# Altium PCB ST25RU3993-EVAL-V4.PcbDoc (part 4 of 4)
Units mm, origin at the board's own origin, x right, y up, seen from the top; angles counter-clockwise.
Board outline 76.25 x 96.25 mm, 6 copper layers (Top Layer, RF GND, Power, GND, Routing, Bottom GND), stack 1.022 mm thick; 319 components, 214 nets, 994 pads, 1429 vias.
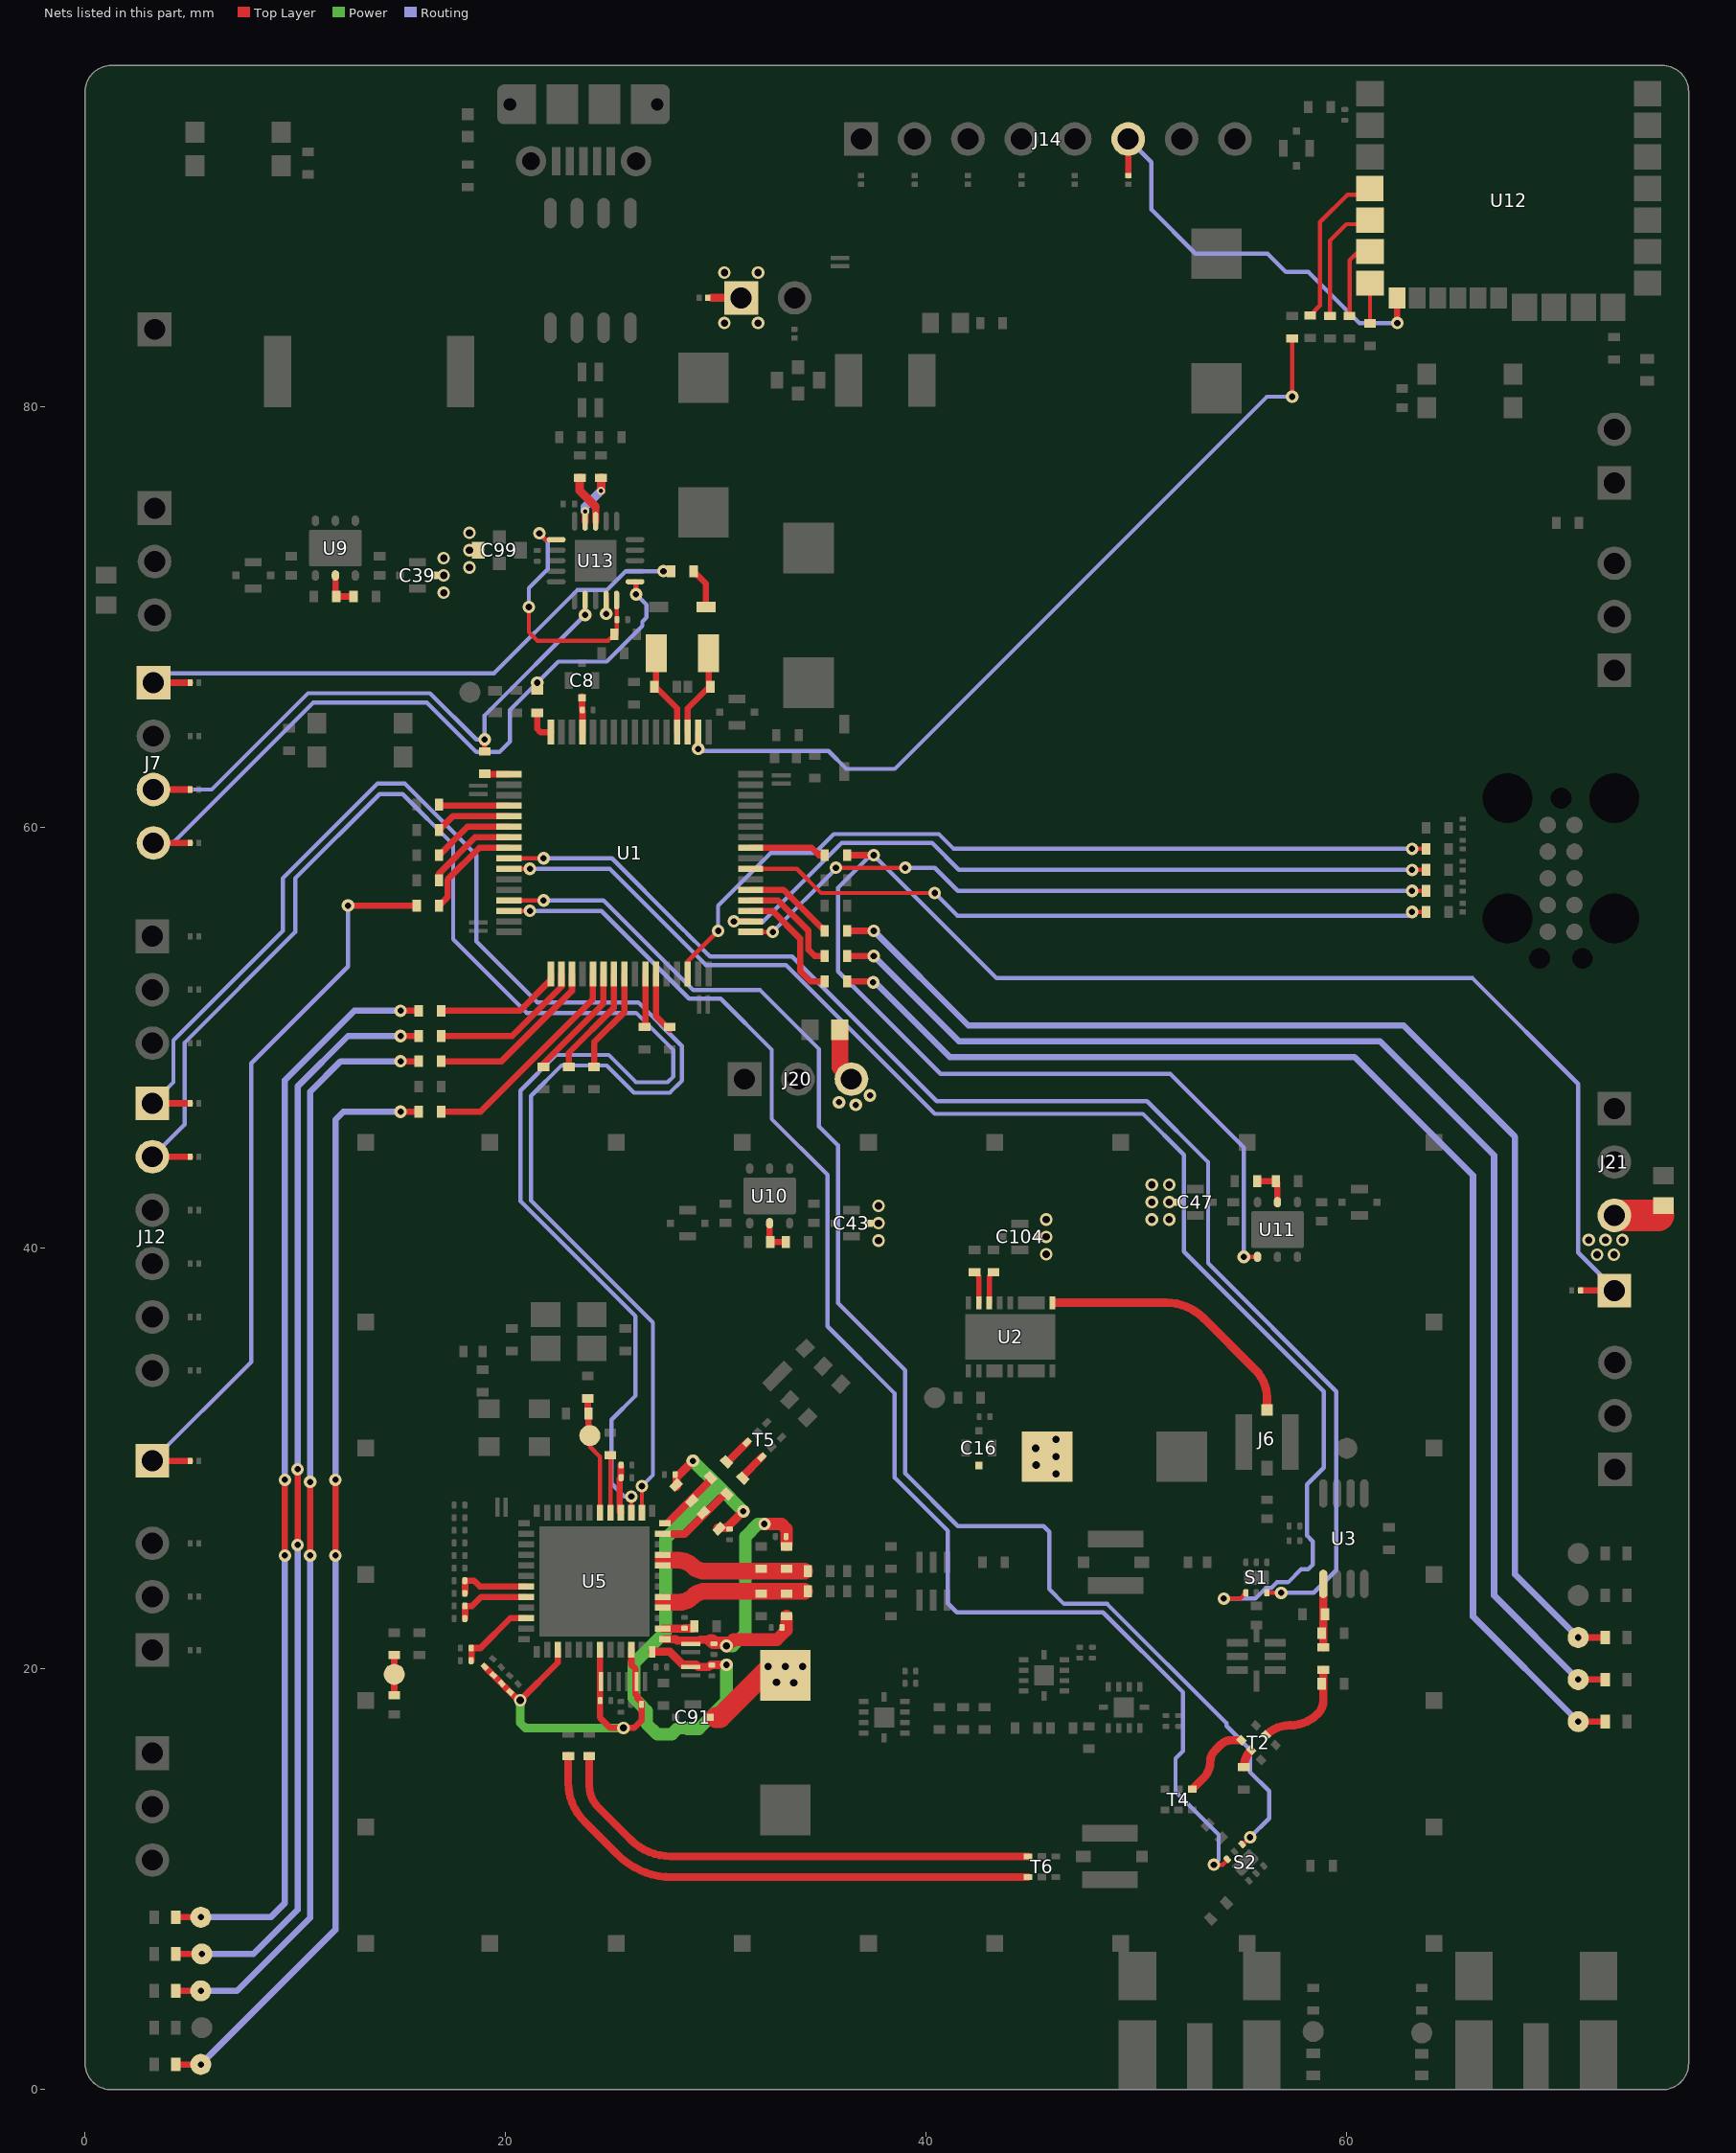
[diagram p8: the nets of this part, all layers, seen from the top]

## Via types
v1: diameter 0.6, hole 0.3, Top Layer to Bottom GND, tented both sides, 407 vias
v2: diameter 0.35, hole 0.35, Top Layer to Bottom GND, tented both sides, 245 vias
v3: diameter 0.61, hole 0.3, Top Layer to Bottom GND, tented both sides, 240 vias
v4: diameter 0.3, hole 0.3, Top Layer to Bottom GND, tented both sides, 105 vias
v5: diameter 0.4, hole 0.3, Top Layer to Bottom GND, tented both sides, 93 vias
v6: diameter 0.6/0.6/0.6/0.6/0.6/0.6 (per signal layer), hole 0.35, Top Layer to Bottom GND, tented both sides, 92 vias
v7: diameter 0.6, hole 0.35, Top Layer to Bottom GND, tented both sides, 71 vias
v8: diameter 0.2, hole 0.2, Top Layer to Bottom GND, tented both sides, 60 vias
v9: diameter 0.4, hole 0.2, Top Layer to Bottom GND, 45 vias
v10: diameter 0.6, hole 0.35, Top Layer to Bottom GND, 16 vias
v11: diameter 0.66, hole 0.33, Top Layer to Bottom GND, tented both sides, 16 vias
v12: diameter 0.35, hole 0.3, Top Layer to Bottom GND, tented both sides, 10 vias
v13: diameter 0.4, hole 0.4, Top Layer to Bottom GND, tented both sides, 6 vias
v14: diameter 1.8/2.51/2.51/2.51/2.51/2.51 (per signal layer), hole 1.71, Top Layer to Bottom GND, 6 vias
v15: diameter 0.5, hole 0.2, Top Layer to Bottom GND, 4 vias
v16: diameter 0.6, hole 0.3, Top Layer to Bottom GND, tented bottom, 4 vias
v17: diameter 0.5, hole 0.3, Top Layer to Bottom GND, tented both sides, 2 vias
v18: diameter 1.8/1.8/1.8/1.8/1.8/2.51 (per signal layer), hole 1.71, Top Layer to Bottom GND, 2 vias
v19: diameter 0.6, hole 0.2, Top Layer to Bottom GND, tented both sides, 2 vias
v20: diameter 0.4, hole 0.2, Top Layer to Bottom GND, tented both sides, 2 vias
v21: diameter 0.8, hole 0.4, Top Layer to Bottom GND, tented both sides, 1 vias

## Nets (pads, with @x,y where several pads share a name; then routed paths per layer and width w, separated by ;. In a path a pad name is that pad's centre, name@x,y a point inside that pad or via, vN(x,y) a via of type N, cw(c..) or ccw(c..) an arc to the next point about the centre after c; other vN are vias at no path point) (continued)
NetR4_2: R4.2 U1.50 | length 35.8
  Top Layer w0.2: v1(63.1,58) R4.2@63.767,58
  Top Layer w0.3: v1(30.85,55.55) U1.50@31.65,55.55
  Routing w0.2: v1(30.85,55.55) 32.25,55.55 35.975,59.275 40.275,59.275 41.55,58 v1(63.1,58)
NetR7_2: R7.2 U1.20 | length 3.3
  Top Layer w0.3: R7.2@16.833,61.1 16.883,61.05 U1.20@20.15,61.05
NetR8_2: R8.2 U1.21 | length 3.6
  Top Layer w0.3: R8.2@16.833,59.9 17.483,60.55 U1.21@20.15,60.55
NetR9_2: R9.2 U1.22 | length 3.9
  Top Layer w0.3: R9.2@16.833,58.7 18.183,60.05 U1.22@20.15,60.05
NetR10_1: R10.1 U2.11 | length 1.5
  Top Layer w0.25: U2.11@43,37.42 43,38.667 R10.1@43.2,38.867
NetR11_2: R11.2 U1.23 | length 4.4
  Top Layer w0.3: R11.2@16.833,57.5 16.833,57.833 18.55,59.55 U1.23@20.15,59.55
NetR12_2: R12.2 U1.42 | length 2.5
  Top Layer w0.3: R12.2@26.6,50.533 26.65,50.583 U1.42@26.65,53.05
NetR13_2: R13.2 U1.43 | length 2.9
  Top Layer w0.3: U1.43@27.15,53.05 27.15,51.05 R13.2@27.8,50.4
NetR19_2: R19.2 U1.46 | length 39.3
  Top Layer w0.2: U1.46@28.65,53.05 28.65,53.65 30,55 v1@30.1,55 ; v1(63.1,59) R19.2@63.767,59
  Routing w0.2: v1@30.1,55 30.1,56.3 32.6,58.8 34.7,58.8 35.6,59.7 40.6,59.7 41.3,59 v1(63.1,59)
  other v1: 30.1,55.1
NetR20_1: R20.1 U2.12 | length 1.5
  Top Layer w0.25: R20.1@42.3,38.867 42.5,38.667 U2.12@42.5,37.42
NetR22_2: R22.2 T2.2 | length 0.8
  Top Layer w0.4: R22.2@55.1,15.333 cw(c56.226,15.333) T2.2@55.401,16.099
NetR23_2: R23.2 R24.1 R25.2 U3.1 | length 3
  Top Layer w0.4: R24.1@58.879,21.033 U3.1@58.879,24.05
NetR24_2: R24.2 R45.2 T2.5 | length 4.8
  Top Layer w0.4: T2.5@56.202,16.9 cw(c57.297,15.703) 57.297,17.325 ccw(c57.297,19.204) 58.625,17.875 ccw(c58.013,18.488) 58.879,18.488 R24.2@58.879,19.967
NetR27_2: R27.2 R44.1 U9.5 | length 1.8
  Top Layer w0.3: R44.1@11.9,71.033 U9.5@11.9,72 ; R44.1@11.938,71 R27.2@12.767,71
NetR28_1: R28.1 R29.2 U10.5 | length 1.7
  Top Layer w0.3: U10.5@32.55,41.2 32.55,40.381 ccw(c32.664,40.381) 32.583,40.3 32.583,40.347 32.631,40.3 R29.2@33.317,40.3
NetR30_1: R30.1 R31.2 U11.5 | length 1.9
  Top Layer w0.3: R31.2@55.733,43.2 R30.1@56.621,43.2 56.7,43.121 U11.5@56.7,42.2
NetR38_1: R38.1 U1.38 | length 5.6
  Top Layer w0.3: R38.1@21.8,48.633 21.8,48.8 24.65,51.65 U1.38@24.65,53.05
NetR39_1: R39.1 U1.39 | length 5.3
  Top Layer w0.3: R39.1@23,48.633 23,49.3 25.15,51.45 U1.39@25.15,53.05
NetR40_1: R40.1 U1.40 | length 5
  Top Layer w0.3: R40.1@24.2,48.633 24.2,49.8 25.65,51.25 U1.40@25.65,53.05
NetR41_2: R41.2 U13.9 | length 2.4
  Top Layer w0.35: U13.9@23.775,74.575 v20(23.775,75.05)
  Top Layer w0.41: v20(24.53,76.025) R41.2@24.53,76.642
  Routing w0.41: v20(23.775,75.05) 23.775,75.27 v20(24.53,76.025)
NetR42_2: R42.2 U1.49 | length 33.9
  Top Layer w0.2: U1.49@31.65,55.05 v1(32.7,55.05) ; v1(35.7,58.1) v1(39,58.1) ; v1(63.1,57) R42.2@63.767,57
  Routing w0.2: v1(32.7,55.05) 35.7,58.05 v1(35.7,58.1) ; v1(39,58.1) 40.4,58.1 41.5,57 v1(63.1,57)
NetR43_2: R43.2 U1.57 | length 3.7
  Top Layer w0.3: U1.57@31.65,59.05 34.55,59.05 34.9,58.7 R43.2@35.167,58.7
NetR46_2: R46.2 U1.55 | length 33.1
  Top Layer w0.2: U1.55@31.65,58.05 33.85,58.05 35,56.9 v1(40.4,56.9) ; v1(63.1,56) R46.2@63.767,56
  Routing w0.2: v1(40.4,56.9) 41.475,55.825 62.925,55.825 v1(63.1,56)
NetR47_2: R47.2 U13.8 | length 2.4
  Top Layer w0.35: U13.8@24.275,74.575 24.275,75.27
  Top Layer w0.41: R47.2@23.52,76.642 23.52,76.025 24.275,75.27
NetR56_2: R56.2 U1.16 | length 1.5
  Top Layer w0.3: R56.2@21.5,65.467 21.5,64.7 21.65,64.55 U1.16@22.15,64.55
NetR57_2: R57.2 U1.17 | length 1.2
  Top Layer w0.3: R57.2@19,62.567 19.017,62.55 U1.17@20.15,62.55
NetR58_1: R58.1 U1.24 | length 4.9
  Top Layer w0.3: R58.1@16.833,56.3 17.233,56.7 17.233,57.533 18.75,59.05 U1.24@20.15,59.05
NetR72_1: R72.1 U12.14 | length 1.9
  Top Layer w0.2: R72.1@61.1,83.983 U12.14@61.1,85.9
NetR73_1: R73.1 U12.13 | length 3.8
  Top Layer w0.2: R73.1@60.125,84.333 60.125,86.975 60.45,87.3 U12.13@61.1,87.3
NetR74_1: R74.1 U1.2 | length 39.5
  Top Layer w0.2: v1(57.4,80.5) R74.1@57.4,83.267
  Top Layer w0.3: v1(29.15,63.75) U1.2@29.15,64.55
  Routing w0.2: v1(29.15,63.75) 29.25,63.65 35.35,63.65 36.2,62.8 38.5,62.8 56.2,80.5 v1(57.4,80.5)
NetR75_1: R75.1 U12.12 | length 5.8
  Top Layer w0.2: R75.1@59.2,84.333 59.2,87.925 59.975,88.7 U12.12@61.1,88.7
NetR76_1: R76.1 U12.11 | length 7.5
  Top Layer w0.2: R76.1@58.25,84.358 58.725,84.833 58.725,88.8 60.025,90.1 U12.11@61.092,90.1
NetS1_1: S1.1 U1.26 | length 66.7
  Top Layer w0.2: U1.26@20.15,58.05 v1(21.15,58.05) ; v16(54.15,23.35) 54.925,23.35 S1.1@55.2,23.625
  Routing w0.2: v1@20.95,58.05 v1(21.15,58.05) 24.95,58.05 29.522,53.478 33.322,53.478 40.4,46.4 50.3,46.4 52.25,44.45 52.25,39.85 58.9,33.2 58.9,29.575 58.1,28.775 58.1,26.347 58.375,26.072 58.375,24.963 58.158,24.747 57.822,24.747 57.2,24.125 56.668,24.125 56.393,23.85 56.15,23.85 55.65,23.35 v16(54.15,23.35)
NetS1_3: S1.3 U1.25 | length 64.9
  Top Layer w0.2: U1.25@20.15,58.55 v1(21.8,58.55) ; S1.3@56.2,23.625 v16(56.875,23.625)
  Routing w0.2: v1(21.8,58.55) 25.05,58.55 28.2,55.4 28.2,55.393 28.493,55.1 28.5,55.1 28.7,54.9 28.7,54.893 28.993,54.6 29,54.6 29.3,54.3 29.3,54.293 29.593,54 29.6,54 29.722,53.878 33.622,53.878 40.5,47 50.5,47 53.4,44.1 53.4,39.3 59.5,33.2 59.5,24.7 58.425,23.625 v16(56.875,23.625)
NetS2_1: S2.1 U1.29 | length 68.5
  Top Layer w0.2: U1.29@20.15,56.55 v1(21.8,56.55) ; S2.1@55.041,11.666 55.066,11.666 v16(55.4,12)
  Routing w0.2: v1(21.8,56.55) 24.65,56.55 28.922,52.278 32.097,52.278 34.9,49.475 34.9,45.8 35.8,44.9 35.8,37.4 39,34.2 39,29.3 41.5,26.8 45.575,26.8 45.85,26.525 45.85,26.214 45.845,26.209 45.845,23.805 46.55,23.1 48.6,23.1 54.273,17.427 54.273,17.292 55.4,16.164 55.4,15.1 56.3,14.2 56.3,12.9 v16(55.4,12)
NetS2_3: S2.3 U1.30 | length 68.2
  Top Layer w0.2: U1.30@20.15,56.05 v1(21.15,56.05) ; v16(53.675,10.7) 54.1,10.7 54.334,10.934 S2.3@54.334,10.959
  Routing w0.2: v1@20.95,56.05 v1(21.15,56.05) 24.55,56.05 28.722,51.878 30.222,51.878 32.65,49.45 32.65,46.15 35.3,43.5 35.3,36.3 38.5,33.1 38.5,29.1 41.025,26.575 41.025,23.125 41.45,22.7 48.4,22.7 52.2,18.9 52.2,16.1 51.85,15.75 51.85,14.175 53.9,12.125 53.9,10.925 v16(53.675,10.7)
NetT2_1: T2.1 T4.1 | length 3.4
  Top Layer w0.4: T4.1@52.732,14.367 53.189,14.824 ccw(c52.438,15.575) 53.5,15.575 cw(c54.285,15.575) 53.73,16.13 54.025,16.425 cw(c54.488,15.962) 54.488,16.617 T2.1@54.875,16.617
NO_RESP: D12.2 R65.2 TP16.1 | length 52.9
  Top Layer w0.3: D12.2@4.32,4.7 v1(5.5,4.7) ; v1(10.7,25.4) v1(10.7,28.9) ; v1(15,48.9) R65.2@15.867,48.9
  Routing w0.3: v1(5.5,4.7) 7.225,4.7 10.7,8.175 v1(10.7,25.4) ; v1(10.7,28.9) 10.7,47.45 12.15,48.9 v1(15,48.9)
NO_RESP_LED: R65.1 U1.35 | length 8.4
  Top Layer w0.3: R65.1@16.933,48.9 19.8,48.9 23.15,52.25 U1.35@23.15,53.05
NRESET: D44.1 J14.6 U12.19 | length 20.7
  Top Layer w0.3: D44.1@49.6,91.006 J14.6@49.6,92.75 ; U12.19@62.385,85.2 62.385,84.015 v1(62.4,84)
  Routing w0.2: J14.6@49.6,92.75 50.7,91.65 50.7,89.4 52.8,87.3 56.225,87.3 57.1,86.425 58.175,86.425 60.6,84 v1(62.4,84)
OAD: D34.1 J12.2 U5.27 | length 78.5
  Top Layer w0.2: U5.27@25.975,27.425 v1(25.975,28.2)
  Top Layer w0.3: J12.2@3.2,44.36 D34.1@4.994,44.36
  Routing w0.2: J12.2@3.2,44.36 4.725,45.885 4.725,49.775 10,55.05 10,57.6 14,61.6 15.1,61.6 17.5,59.2 17.5,54.7 21,51.2 26.2,51.2 27.975,49.425 27.975,48.175 27.7,47.9 26.2,47.9 24.9,49.2 22.4,49.2 20.7,47.5 20.7,42.25 26.175,36.775 26.175,33 25.025,31.85 25.025,28.825 25.65,28.2 v1(25.975,28.2) v1@25.975,28.1
OAD2: D33.1 J12.1 U5.26 | length 76.3
  Top Layer w0.2: U5.26@26.475,27.425 v1(26.475,28.7)
  Top Layer w0.3: J12.1@3.2,46.9 D33.1@4.994,46.9
  Routing w0.2: J12.1@3.2,46.9 4.2,47.9 4.2,49.9 9.4,55.1 9.4,57.6 13.9,62.1 15.2,62.1 18.6,58.7 18.6,54.6 21.5,51.7 26.3,51.7 28.375,49.625 28.375,47.975 27.8,47.4 26.1,47.4 24.8,48.7 22.65,48.7 21.2,47.25 21.2,42.275 27,36.475 27,29.225 v1(26.475,28.7) v1@26.475,28.5
OSC: D8.2 R53.2 TP13.1 | length 52.6
  Top Layer w0.3: D8.2@4.32,6.45 v1(5.55,6.45) ; v1(10.1,25.9) v1(10.1,29.5) ; v1(15,50.1) R53.2@15.867,50.1
  Routing w0.3: v1(5.55,6.45) 8,6.45 10.1,8.55 v1(10.1,25.9) ; v1(10.1,29.5) 10.1,47.7 12.5,50.1 v1(15,50.1)
OSC32_IN: C9.1 U1.3 X1.1 | length 4.2
  Top Layer w0.3: U1.3@28.65,64.55 28.65,65.679 29.65,66.679 X1.1@29.65,68.3
OSC32_OUT: C10.1 U1.4 X1.2 | length 4.2
  Top Layer w0.3: X1.2@27.15,68.3 27.15,66.679 28.15,65.679 U1.4@28.15,64.55
OSC_LED: R53.1 U1.34 | length 7.3
  Top Layer w0.3: R53.1@16.933,50.1 20.303,50.1 22.65,52.447 U1.34@22.65,53.05
OSCI: R55.2 U5.29 | length 2.7
  Top Layer w0.2: U5.29@24.975,27.425 R55.2@24.975,30.167
OSCO: C51.2 R54.1 TP1.1 U5.30 | length 5.7
  Top Layer w0.2: TP1.1@24,31.1 24,30.575 24.475,30.1 U5.30@24.475,27.425
  Top Layer w0.3: R54.1@23.9,32.867 23.9,32.188 C51.2@23.933,32.154 23.933,31.167 TP1.1@24,31.1
PA_LDO_EN: D45.1 J4.1 R43.1 U11.1 | length 86.4
  Top Layer w0.2: v1(55.1,39.6) U11.1@55.75,39.6
  Top Layer w0.3: R43.1@36.233,58.7 v1(37.5,58.7) ; D45.1@71.106,38 J4.1@72.725,38 J4.1@72.75,38
  Routing w0.2: v1(55.1,39.6) 55.1,44.8 51.6,48.3 40.675,48.3 35.8,53.175 35.8,57.15 37.35,58.7 v1(37.5,58.7) 37.5,58.693 43.343,52.85 53.15,52.85 65.975,52.85 71,47.825 71,39.8 J4.1@72.775,38.025
PA_OUT: J6.IN U2.7 | length 12.8
  Top Layer w0.4: U2.7@46.1,37.42 51.403,37.42 cw(c51.403,34.88) 53.199,36.676 55.65,34.225 cw(c54.322,32.897) 56.2,32.897 J6.IN@56.2,32.325
PAOUT_N: C1.1 C4.1 L1.1 U5.16 U5.17 | length 6.8
  Top Layer w0.8: 27.5,23.175 28.236,23.175 ccw(c28.236,24.114) 28.9,23.45 cw(c29.504,22.846) 29.504,23.7 C4.1@34.2,23.7
PAOUT_P: C3.1 C5.1 L2.2 U5.20 U5.21 | length 6.8
  Top Layer w0.8: 27.5,25.175 28.211,25.175 cw(c28.211,24.236) 28.875,24.9 ccw(c29.479,25.504) 29.479,24.65 C5.1@34.2,24.65
PLL: D7.2 R52.2 TP12.1 | length 52.3
  Top Layer w0.3: D7.2@4.32,8.2 v1(5.5,8.2) ; v1(9.5,25.4) v1(9.5,29) ; v1(15,51.3) R52.2@15.867,51.3
  Routing w0.3: v1(5.5,8.2) 8.825,8.2 9.5,8.875 v1(9.5,25.4) ; v1(9.5,29) 9.5,48 12.8,51.3 v1(15,51.3)
PLL_LED: R52.1 U1.33 | length 6.1
  Top Layer w0.3: R52.1@16.933,51.3 20.675,51.3 22.15,52.775 U1.33@22.15,53.05
RESET: D9.2 R36.2 | length 1.9
  Top Layer w0.3: R36.2@28.931,72.2 29.525,71.606 D9.2@29.525,70.5
RF: D3.2 R17.2 TP10.1 | length 62.9
  Top Layer w0.3: R17.2@36.233,52.7 v1@37.5,52.7 ; v1(71,17.5) D3.2@72.28,17.5
  Routing w0.3: v1(37.475,52.65) 37.567,52.65 41.117,49.1 60.367,49.1 66,43.467 66,22.5 v1(71,17.5)
RF_LED: R17.1 U1.51 | length 5.8
  Top Layer w0.3: U1.51@31.65,56.05 32.686,56.05 34,54.736 34,53.2 34.5,52.7 R17.1@35.167,52.7
RFO_N: C54.1 L4.1 U5.23 | length 3.4
  Top Layer w0.37: 27.95,26.425 28.512,26.425 30.41,28.323 C54.1@30.523,28.323
RFO_P: C65.1 L3.2 U5.24 | length 2.9
  Top Layer w0.37: U5.24@27.741,26.984 29.745,28.988 C65.1@29.745,29.101
RTS: D47.1 J7.1 R36.1 U13.19 | length 30.3
  Top Layer w0.25: v1(24.775,70.175) U13.19@24.775,70.825 ; v1(27.5,72.2) R36.1@27.864,72.2
  Top Layer w0.3: J7.1@3.251,66.9 D47.1@4.994,66.9
  Routing w0.2: J7.1@3.251,66.9 3.701,67.35 19.45,67.35 23.4,71.3 24.75,71.3 24.775,71.275 ; v1(24.775,70.175) 24.775,71.275 ; v1(27.5,72.2) 25.7,72.2 24.775,71.275
RX: D50.1 J7.4 R56.1 U13.1 | length 34.7
  Top Layer w0.25: R56.1@21.5,66.533 v1(21.5,66.9) ; U13.1@26.15,71.7 26.2,71.65 v1@26.2,71.3
  Top Layer w0.3: J7.4@3.251,59.28 D50.1@4.994,59.28
  Routing w0.2: J7.4@3.251,59.28 4.18,59.28 10.85,65.95 16.25,65.95 18.6,63.6 19.7,63.6 20.2,64.1 20.2,65.6 v1(21.5,66.9) 22.5,67.9 24.8,67.9 26.5,69.6 26.5,69.807 26.7,70.007 26.7,70.6 v1(26.2,71.1)
RX_N: C94.1 T6.3 | length 23.8
  Top Layer w0.37: C94.1@23.975,15.867 23.975,14.451 ccw(c25.426,14.451) 24.4,13.425 25.928,11.897 ccw(c27.865,13.835) 27.865,11.095 T6.3@44.84,11.095
RX_P: C93.1 T6.4 | length 25.4
  Top Layer w0.37: C93.1@22.975,15.867 22.975,14.596 ccw(c25.571,14.596) 23.735,12.76 25.321,11.174 ccw(c27.903,13.756) 27.903,10.105 T6.4@44.84,10.105
TAG: D6.2 R51.2 TP8.1 | length 52.9
  Top Layer w0.3: D6.2@4.32,1.2 v1(5.5,1.2) ; v1(11.9,25.4) v1(11.9,29) ; v1(15,46.5) R51.2@15.867,46.5
  Routing w0.3: v1(5.5,1.2) 11.9,7.6 v1(11.9,25.4) ; v1(11.9,29) 11.9,46.117 12.283,46.5 v1(15,46.5)
TAG_LED: R51.1 U1.37 | length 10.6
  Top Layer w0.3: R51.1@16.933,46.5 18.8,46.5 24.15,51.85 U1.37@24.15,53.05
TUNED: D11.2 R64.2 TP9.1 | length 62.6
  Top Layer w0.3: R64.2@36.233,53.9 v1(37.5,53.9) ; v1(71,19.5) D11.2@72.28,19.5
  Routing w0.3: v1(37.5,53.9) 41.55,49.85 61.575,49.85 67,44.425 67,23.5 v1(71,19.5)
TUNED_LED: R64.1 U1.52 | length 5.1
  Top Layer w0.3: U1.52@31.65,56.55 32.95,56.55 34.4,55.1 34.4,54.2 34.7,53.9 R64.1@35.167,53.9
TUNING: D5.2 R50.2 TP7.1 | length 62.1
  Top Layer w0.3: R50.2@36.233,55.1 v1(37.5,55.1) ; v1(71,21.5) D5.2@72.28,21.5
  Routing w0.3: v1(37.5,55.1) 42,50.6 42.8,50.6 61.225,50.6 62.7,50.6 68,45.3 68,24.5 v1(71,21.5)
TUNING_LED: R50.1 U1.53 | length 4.3
  Top Layer w0.3: U1.53@31.65,57.05 33.217,57.05 R50.1@35.167,55.1
TX: D49.1 J7.3 R57.1 U13.17 | length 28.8
  Top Layer w0.25: R57.1@19,63.633 v1(19,64.2)
  Top Layer w0.3: J7.3@3.251,61.82 D49.1@4.994,61.82
  Routing w0.2: J7.3@3.251,61.82 6.02,61.82 10.6,66.4 16.4,66.4 18.6,64.2 v1(19,64.2) 19,65.35 v1(23.775,70.125)
TX_N: C54.2 T5.4 | length 1.4
  Top Layer w0.37: C54.2@31.277,29.077 31.277,29.177 T5.4@32.183,30.083
TX_P: C65.2 T5.3 | length 1.4
  Top Layer w0.37: C65.2@30.527,29.827 T5.3@31.483,30.783
UART_LOG_TX: D52.1 J11.1 R58.2 | length 35.3
  Top Layer w0.3: J11.1@3.2,29.9 D52.1@4.994,29.9 ; v1(12.5,56.3) R58.2@15.767,56.3
  Routing w0.2: J11.1@3.2,29.9 7.9,34.6 7.9,48.8 12.5,53.4 v1(12.5,56.3)
UReset: C33.1 R6.2 U13.11 U13.20 | length 12.3
  Top Layer w0.2: v1(21.1,70.5) 21.1,69.3 21.5,68.9 24.867,68.9 R6.2@25.167,69.2 ; v1(21.6,74) 21.9,73.7 U13.11@22.4,73.7 ; R6.2@25.167,69.1 25.275,69.208 U13.20@25.275,70.825
  Routing w0.2: v1(21.1,70.5) 21.1,71.4 22,72.3 22,73.6 v1(21.6,74)
VBPD: C34.1 C52.2 U5.28 | length 2.3
  Top Layer w0.3: U5.28@25.475,27.425 25.425,27.475 25.425,29.05 25.475,29.1 C52.2@25.475,29.7
VBUS: C39.1 C43.1 C47.1 C99.1 D20.1 P2.1 | length 1.4
  Top Layer w0.4: 29.8,85.2 29.9,85.2 P2.1@31.2,85.2
  other v6: 37.725,40.375 51.55,43.025 17.05,71.175 18.275,74.025 30.4,84 32,84
  other v7: 37.725,41.2 50.725,41.375 51.55,41.375 37.725,42.025 50.725,42.2 51.55,42.2 50.725,43.025 17.05,72 18.275,72.375 17.05,72.825 18.275,73.2 30.4,86.4 32,86.4
VCO: C55.1 R33.1 TP2.1 | length 1.9
  Top Layer w0.3: C55.1@14.7,18.754 14.7,19.7 R33.1@14.7,20.667
VDD_A: C73.1 C74.1 U5.44 | length 3.7
  Top Layer w0.3: C73.1@18.07,22.4 18.07,23 18.4,23 18.825,23.425 U5.44@20.975,23.425
VDD_B: C57.2 C58.1 C77.1 C78.1 L3.1 L4.2 U5.12 | length 30
  Top Layer w0.4: U5.12@26.975,20.825 27.8,20.825 28.425,20.2 29.051,20.2 29.151,20.1 29.374,20.1 29.648,20.1 29.749,20.2 v1(30.5,20.2) ; L3.1@28.123,28.677 28.123,29.123 v1(28.9,29.9) ; L4.2@30.077,26.723 30.523,26.723 v1(31.3,27.5)
  Power w0.6: v1(28.9,29.9) 30.1,28.7 ; v1(30.5,20.2) 30.5,18.475 29.175,17.15 28.672,17.15 28.622,17.2 28.2,17.2 27.9,16.9 27.2,16.9 26.7,17.4 26.7,18 26.514,18.186 26.514,18.204 26.1,18.619 26.1,20.275 27.6,21.775 27.6,26.2 30.1,28.7 ; v1(31.3,27.5) 30.1,28.7
VDD_MIX: C79.2 C80.2 C81.2 C82.2 C83.2 C84.2 C85.1 C86.1 U5.3 U5.7 U5.10 | length 20.7
  Top Layer w0.3: C79.2@19.009,20.109 C82.2@20.209,18.909 20.6,18.518 v6(20.693,18.518) 22.475,20.3 U5.3@22.475,20.925 ; U5.7@24.475,20.925 24.475,17.7 24.975,17.2 v6(25.6,17.2) 26.1,17.2 26.47,17.57 26.47,18.4 26.271,18.599 26.271,18.706 26.175,18.801 26.175,20.004 25.975,20.204 U5.10@25.975,20.925
  Power w0.4: v6(20.693,18.518) 20.693,17.432 20.925,17.2 v6(25.6,17.2)
VDD_PA: C12.1 C14.2 C66.1 C67.1 L1.2 L2.1 U5.13 | length 16.1
  Top Layer w0.4: U5.13@27.575,21.425 28.075,21.425 28.15,21.35 29.201,21.35 29.251,21.4 29.749,21.4 29.798,21.351
  Top Layer w0.6: C66.1@29.9,21.27 29.819,21.351 29.798,21.351 29.749,21.351 29.844,21.255 30.5,21.255 v6(30.5,21.1) 30.53,21.1 30.83,21.4 32.9,21.4 33.35,21.85 L1.2@33.35,22.517 ; v1(32.3,26.9) 33.115,26.9 33.35,26.665 L2.1@33.35,25.9
  Power w0.6: v6(30.5,21.1) 30.8,21.1 31.4,21.7 31.4,26.3 32,26.9 v1(32.3,26.9)
VDDA: C8.3 C26.1 U1.13 | length 1.7
  Top Layer w0.3: C26.1@23.63,65.6 23.65,65.58 U1.13@23.65,64.55 ; C26.1@23.63,65.6 C8.3@23.63,66.175 C8.3@23.63,66.24
VDDLF: C75.1 C76.1 U5.46 | length 3.8
  Top Layer w0.3: C75.1@18.37,20.4 18.37,21 18.8,21 20.225,22.425 U5.46@20.975,22.425
VEXT_PA: C90.1 FB1.1 U5.14 | length 1.5
  Top Layer w0.4: U5.14@27.475,21.925 28.495,21.925 28.5,21.93 28.867,21.93 FB1.1@28.967,22.03
VOSC: C71.1 C72.1 U5.43 | length 3.6
  Top Layer w0.3: C71.1@18.07,23.6 18.07,24.2 18.5,24.2 18.775,23.925 U5.43@20.975,23.925
VPA: C16.3 C20.1 C104.1 J21.3 R3.1 | length 2.1
  Top Layer w1.5: J21.3@72.725,41.57 74.82,41.57
  other v6: 71.9,39.7 72.7,39.7 45.7,39.725 71.5,40.4 72.3,40.4 73.1,40.4
  other v7: 46.175,29.275 45.225,29.7 46.175,30.1 45.2,30.5 46.175,30.925 45.7,40.55 45.7,41.375
VSUP: C91.3 C92.1 J20.3 R2.1 | length 5.9
  Top Layer w0.8: R2.1@35.886,50.4 35.886,48.619 J20.3@36.455,48.05
  Top Layer w1: 30,17.7 30.2,17.7 C92.1@32.434,19.934
  other v1: 36.65,46.825 35.85,46.95 37.325,47.275
  other v7: 33.7,19.35 32.875,19.375 32.475,20.125 33.3,20.125 34.125,20.125
pads on no net: P1. P1.4 P3. P3.7 P3.9 P3.A P3.B P3.C T1.2 T1.6 T3.6 T5.6 T6.6 U1.5 U1.6 U1.8 U1.9 U1.10 U1.11 U1.41 U3.6 U5.36 U9.3 U10.3 U11.3 U12.2 U12.3 U12.4 U12.5 U12.6 U12.15 U12.16 U12.17 U12.18 U13.2 U13.4 U13.5 U13.6 U13.7 U13.14 U13.16

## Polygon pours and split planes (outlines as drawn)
GND on Top Layer "Top GND" (solid, pour order 43): 0,1.25 0,95 cw(c1.25,95) 1.25,96.25 75,96.25 cw(c75,95) 76.25,95 76.25,1.25 cw(c75,1.25) 75,0 1.25,0 cw(c1.25,1.25)
NetP1_1 on Top Layer "5V" (solid, pour order 10): 24.8,92.7 25.1,93 28,93 28,89 27.5,88.5 25.5,88.5 25.5,90.4 24.8,91.1
NetC23_1 on Top Layer "5V_ESD" (solid, pour order 42): 32.5,80.2 33.2,80.9 33.2,81.7 32.5,82.4 29.2,82.4 27.1,84.5 25.6,84.5 25.6,83.2 28.6,80.2
NetP1_5 on Top Layer "USB_GND" (solid, pour order 12): 22.6,92.7 22.3,93 19.4,93 19.4,89 19.9,88.5 22.6,88.5 22.6,91.1
GND on RF GND "RF GND" (solid, pour order 44): 0.125,1.3 0,95 cw(c1.187,94.937) 1.25,96.125 75,96.25 cw(c74.963,95.038) 76.175,95 76.25,1.25 cw(c75.05,1.3) 75,0.1 1.25,0 cw(c1.337,1.212)
VPA on Power "VPA" (solid, pour order 55): 37.653,26.325 37.653,38.903 41.265,42.515 46.285,42.515 48.175,40.625 69.875,40.625 71.875,42.625 73.875,42.625 73.875,26.325
3V3 on Power "RF GND" (solid, pour order 65): 0,1.25 0,95 cw(c1.25,95) 1.25,96.25 75,96.25 cw(c75,95) 76.25,95 76.25,1.25 cw(c75,1.25) 75,0 1.25,0 cw(c1.25,1.25)
VSUP on Power "VSUP" (solid, pour order 63): 34.9,48.2 28.9,42.2 28.9,31 32.8,27.1 32.8,22.6 31,20.8 31,19.1 36.4,19.1 37.5,20.2 37.5,49.3 34.9,49.3
NetC45_3 on Power "3.6V" (solid, pour order 59): 26,39.8 26,46.2 29.1,49.3 33.4,49.3 34.8,49.3 34.8,48.3 34.8,46.5 33,46.5 28.5,42 28.5,39.8 27.5,39.8
NetC49_3 on Power "4.7V" (solid, pour order 53): 71.875,42.875 69.875,40.875 61.5,40.875 61.5,47.7 73.875,47.7 73.875,42.875
VBUS on Power "VBUS" (solid, pour order 61): 15,70 19.3,70 36.5,70 40.6,65.9 40.6,52.4 37.3,49.1 37.3,39.5 40.75,39.5 43.25,42 47.1,42 48.175,40.925 48.25,41 61.4,41 61.4,70.1 44.5,87 26.5,87 15,75.5
GND on GND "GND" (solid, pour order 51): 0,1.25 0.175,95 cw(c1.337,95.087) 1.25,96.25 75,96.2 cw(c75.025,94.975) 76.25,95 76.15,1.25 cw(c74.925,1.225) 74.95,0 1.25,0.075 cw(c1.212,1.287)
GND on Routing "Routing" (solid, pour order 48): 0,1.25 0,95 cw(c1.25,95) 1.25,96.25 75,96.25 cw(c75,95) 76.25,95 76.25,1.25 cw(c75,1.25) 75,0 1.25,0 cw(c1.25,1.25)
GND on Bottom GND "Bottom GND" (solid, pour order 47): 0,1.25 0,95 cw(c1.25,95) 1.25,96.25 75,96.25 cw(c75,95) 76.25,95 76.25,1.25 cw(c75,1.25) 75,0 1.25,0 cw(c1.25,1.25)

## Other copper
Top Layer:
  region net VBUS: 17.975,74.475 16.9,73.4 16.9,71.175 17.35,70.725 18.425,71.8 18.425,74.475
  pour cut-out: 50.017,9.619 50.042,12.574 47.424,12.575 47.414,9.622
  region net VBUS: 18.925,73.05 18.85,72.975 18.425,71.925 17.975,71.925 17.975,73.2 18.925,73.2
  region net VBUS: 18.925,73.35 18.85,73.425 18.425,74.475 17.975,74.475 17.975,73.2 18.925,73.2
  region net VPA: 45.05,40.7 45.125,40.775 45.55,41.825 46,41.825 46,40.55 45.05,40.55
  region net VPA: 45.05,40.4 45.125,40.325 45.55,39.275 46,39.275 46,40.55 45.05,40.55
  region net VPA: 42.3,29.85 42.3,28.3 42.8,27.8 46.7,27.8 46.7,29.9 42.35,29.9
  region net VBUS: 52.2,42.35 52.125,42.425 51.7,43.475 50.4,43.475 50.4,42.2 52.2,42.2
  region net VBUS: 52.2,42.05 52.125,41.975 51.7,40.925 50.4,40.925 50.4,42.2 52.2,42.2
  region net VBUS: 37.05,41.05 37.125,40.975 37.55,39.925 38,39.925 38,41.2 37.05,41.2
  region net VBUS: 37.05,41.35 37.125,41.425 37.55,42.475 38,42.475 38,41.2 37.05,41.2
  region net VBUS: 16.4,71.85 16.475,71.775 16.9,70.725 17.35,70.725 17.35,72 16.4,72
  region net VBUS: 16.4,72.15 16.475,72.225 16.9,73.275 17.35,73.275 17.35,72 16.4,72
  region net NetC49_3: 61.2,42.05 61.275,41.975 61.7,40.925 63,40.925 63,42.2 61.2,42.2
  region net NetC49_3: 61.2,42.35 61.275,42.425 61.7,43.475 63,43.475 63,42.2 61.2,42.2
  region net NetC45_3: 28.05,41.05 27.975,40.975 27.55,39.925 27.1,39.925 27.1,41.2 28.05,41.2
  region net NetC45_3: 28.05,41.35 27.975,41.425 27.55,42.475 27.1,42.475 27.1,41.2 28.05,41.2
  pour cut-out: 36.376,33.573 34.311,35.674 32.215,33.579 34.289,31.491
  pour cut-out: 57.701,32.102 54.746,32.127 54.745,29.509 57.699,29.498
  pour cut-out: 47.708,26.551 47.683,23.596 50.301,23.595 50.311,26.548
  pour cut-out: 61.792,96.25 61.792,92 73.592,92 73.592,96.25
  region net VBUS: 30,86.9 30,83.6 32.4,83.6 32.4,86.9
  region net NetC96_3: 35.7,82.525 34.8,81.625 34.8,80.925 35.7,80.025 35.8,80.025 35.8,82.525
  region net 3V3: 31.65,65.7 32.15,66.2 36.6,66.2 36.6,65.9 36.3,65.6 35.3,65.6 35,65.3 31.65,65.3
  region net 3V3: 2,69 2.3,68.7 4.2,68.7 4.5,69 4.5,71.4 4.2,71.7 2.3,71.7 2,71.4
  region net VPA: 73.55,42.3 73.55,39.925 72.95,39.325 71.675,39.325 71.1,39.9 71.1,41.229 72.171,42.3
  region net NetC49_3: 73.667,45.533 74.05,45.15 74.05,43.192 73.706,42.848 71.594,42.848 71.273,43.169 71.273,45.1 71.706,45.533
  region net VSUP: 35.3,48.525 35.3,46.875 35.7,46.475 37.2,46.475 37.625,46.9 37.625,48.65 37.297,48.978 35.753,48.978
  region net NetC45_3: 34.025,49.525 32.825,48.325 32.825,46.675 32.975,46.525 34.95,46.525 34.95,49.05 34.45,49.55 34.025,49.55
  region net GND: 50.129,11.865 50.063,11.8 50.05,11.8 50.05,11.89 50.036,11.904
  region net GND: 46.535,36.79 46.535,36.7 46.125,36.7 46.125,36.79
  region net GND: 46.535,38.05 46.535,38.15 46.15,38.15 46.15,38.05
  region net GND: 41.465,36.79 41.465,36.7 41.875,36.7 41.875,36.79
  region net GND: 41.465,36.794 41.465,36.704 41.875,36.704 41.875,36.794
  region net GND: 35.198,35.389 34.9,35.092 34.9,35.076 34.793,35.183 35.048,35.438 35.149,35.438
  region net GND: 36.089,34.498 35.792,34.2 35.824,34.134 35.883,34.093 36.138,34.348 36.138,34.449
  region net GND: 33.402,31.811 33.667,32.075 33.708,32.075 33.787,31.997 33.552,31.762 33.451,31.762
  region net GND: 32.479,32.671 32.8,32.992 32.8,33 32.79,33 32.75,33.04 32.462,32.751
  region net GND: 33.65,34.25 34.2,34.8 33.825,35.175 33.725,35.175 33.263,34.713 33.263,34.627
  region net GND: 34.8,32 34.4,32.4 34.4,32.425 35.475,33.5 35.5,33.5 35.925,33.075 35.925,33.025 34.9,32
  pour cut-out: 14,22.25 14,18.125 15.375,18.125 15.375,21 16.15,21 16.4,21.25 17.3,21.25 17.375,21.325 18.085,21.325 18.19,21.22 18.384,21.22 18.433,21.268 18.433,22.017 18.4,22.05 16.45,22.05 16.25,22.25
RF GND:
  pour cut-out: 61.792,96.25 61.792,92 73.592,92 73.592,96.25
Power:
  pour cut-out: 45.618,26.325 ccw(c45.481,26.189) 45.481,26.381 45.061,26.381 ccw(c45.061,26.189) 44.925,26.325
  pour cut-out: 61.8,96.25 61.8,92 73.6,92 73.6,96.25
GND:
  pour cut-out: 61.792,96.25 61.792,92 73.592,92 73.592,96.25
Routing:
  pour cut-out: 61.792,96.25 61.792,92 73.592,92 73.592,96.25
Bottom GND:
  pour cut-out: 61.792,96.25 61.792,92 73.592,92 73.592,96.25

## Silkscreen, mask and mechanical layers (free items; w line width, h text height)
Top Overlay:
  drawing of 2709 lines, arcs and shapes, not listed
  text "GND" at 56.181,95.543 h1.1 r180
  text "USB" at 29.4,93 h0.8 r90
  text "3V3" at 53.775,90.775 h1.1 r180
  text "Supply" at 33.2,90.4 h0.8 r90
  text "RST" at 38.3,89.5 h1.1 r180
  text "DI" at 47.725,87.775 h1.1 r90
  text "DO" at 40.125,87.65 h1.1 r90
  text "nR" at 50.15,87.65 h1.1 r90
  text "CK" at 42.625,87.625 h1.1 r90
  text "MS" at 45.175,87.6 h1.1 r90
  text "GND" at 5.625,85.1 h1.1 r270
  text "BT_OK" at 75.8,81.125 h0.8 r90
  text "BT / BOOT" at 66.65,75.897 h1.1
  text "GND" at 5.15,74.8 h1.1
  text "3V3" at 5.025,74.2 h1.1 r270
  text "GND" at 68.091,72.18 h1.1
  text "GND" at 68.091,69.64 h1.1
  text "3V3" at 5.15,69.5 h1.1
  text "MCU OK" at 19.8,67.2 h0.8 r90
  text "GND" at 68.091,67.1 h1.1
  text "RTS" at 5.9,66.5 h1.1
  text "ST25RU3993-EVAL" at 39.608,65.212 h3
  text "DTR" at 5.9,64 h1.1
  text "SWD" at 69.1,63.3 h0.8
  text "www.st.com/ST25R" at 41.373,61.792 h2.5
  text "TX" at 5.8,61.4 h1.1
  text "RX" at 5.9,58.9 h1.1
  text "ETC1" at 6.475,54.475 h1.1
  text "Rev.:B1" at 49.336,53.087 h1.5
  text "ETC2" at 6.5,51.9 h1.1
  text "ETC3" at 6.5,49.4 h1.1
  text "GND" at 29.7,46.9 h1.1 r90
  text "VSUP" at 39.25,46.825 h1.1 r90
  text "OAD2" at 6.5,46.5 h1.1
  text "GND" at 68.091,46.25 h1.1
  text "OAD" at 6.5,44 h1.1
  text "VPA" at 68.091,43.71 h1.1
  text "EN" at 6.6,41.5 h1.1
  text "VPA" at 68.091,41.17 h1.1
  text "IRQ" at 6.5,38.8 h1.1
  text "NCS" at 6.5,36.4 h1.1
  text "PA / LDO / EN" at 65.4,35.175 h1.1
  text "GND" at 68.091,34.18 h1.1
  text "ADC" at 6.5,33.9 h1.1
  text "ATP3" at 36.643,32.513 h0.8
  text "ATP1" at 26.85,32.05 h0.8
  text "GND" at 68.091,31.64 h1.1
  text "ATP4" at 58.809,31.344 h0.8
  text "GND" at 68.091,29.1 h1.1
  text "UART / LOG" at 5.8,28.075 h1.1
  text "MISO" at 6.1,25.6 h1.1
  text "EXT_PA" at 65.383,25.139 h0.8
  text "INT_PA" at 65.517,23.139 h0.8
  text "MOSI" at 6.1,23.1 h1.1
  text "TUNING" at 65.517,21.073 h0.8
  text "CLK" at 6.1,20.5 h1.1
  text "Tuned" at 66.183,19.073 h0.8
  text "RF ON" at 66.183,17.073 h0.8
  text "GND" at 6.1,15.6 h1.1
  text "ATP2" at 16.542,14.276 h0.8 r90
  text "GND" at 6.1,13.1 h1.1
  text "GND" at 6.1,10.6 h1.1
  text "PLL OK" at 6.3,7.803 h1
  text "OSC OK" at 6.3,6.053 h1
  text "No Tag Response" at 6.3,4.436 h1
  text "Tag CRC Error" at 6.3,2.686 h1
  text "Tag found" at 6.3,0.936 h1
  text "ANT2" at 74.742,0.847 h1.1 r90
  text "ANT1" at 47.275,0.796 h1.1 r90
  text "50 Ω" at 48.525,0.725 h1.5 r90
  text "50 Ω" at 75.937,0.725 h1.5 r90
Bottom Solder:
  rectangle: 39.1,32.25 48.9,39.25
  rectangle: 21.35,21.3 27.1,27.05
Board Outline:
  the board outline again, w0.254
